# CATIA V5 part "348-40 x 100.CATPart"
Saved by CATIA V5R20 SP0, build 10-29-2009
Part number: 348-40 x 100
Definition: NONE
Nomenclature: 348-40 x 100
Source: Unknown
Description: 348-40 x 100
Bounding box of the stored display mesh (mm): x 0 to 100, y -27.5 to 27.5, z -27.5 to 27.5
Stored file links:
  C:\Users\Utente\Desktop\IO LAVORO\3D X SITO CF\X SITO\3D files 348\348-40 x 100.CATPart
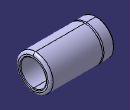
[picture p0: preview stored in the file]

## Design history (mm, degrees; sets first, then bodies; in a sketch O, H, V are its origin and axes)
Body1 "348-40 x 100" (main body)
  Solid1: solid without history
